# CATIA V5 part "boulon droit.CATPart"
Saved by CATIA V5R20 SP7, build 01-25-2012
Part number: boulon droit
Bounding box of the stored display mesh (mm): x 8.673 to 14.247, y 20.422 to 25.578, z -1.221 to 0.279
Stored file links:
  F:\Travaux\Modélisations\CFAO_2011\CFAO_2011_MMS\CFAO_2011_MMS_DONE\CFAO_2011_MMS_jboiteux\Catia\boulon droit.CATPart
  U:\finthinkmotion\stepper.CATProduct
  F:\Travaux\Modélisations\CFAO_2011\CFAO_2011_MMS\CFAO_2011_MMS_DONE\CFAO_2011_MMS_jboiteux\Catia\bati.CATPart
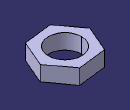
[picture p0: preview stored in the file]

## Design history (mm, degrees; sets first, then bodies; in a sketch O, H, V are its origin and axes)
Parameters
  rayontube = 9 mm {= External.royontubebati}
External parameters (linked from other documents)
  External.royontubebati = 9 mm
Set1
  Plane1: linked copy from another document
  DatumSurface1: linked copy from another document
  Point1: linked copy from another document
Body1 (main body)
  Sketch1 on Plane1, origin (0, 0, -5.7209), H (1, 0, 0), V (0, -1, 0)
    point P1 (11.46, -23)
    point P2 (13.1382, -20.7512)
    point P3 (10.3516, -20.4223)
    point P4 (8.6734, -22.671)
    point P5 (9.7818, -25.2488)
    point P6 (12.5684, -25.5777)
    point P7 (14.2466, -23.329)
    point P8 (11.7449, -20.5868)
    line L1 (13.1382, -20.7512) -> (10.3516, -20.4223)
    line L2 (10.3516, -20.4223) -> (8.6734, -22.671)
    line L3 (8.6734, -22.671) -> (9.7818, -25.2488)
    line L4 (9.7818, -25.2488) -> (12.5684, -25.5777)
    line L5 (12.5684, -25.5777) -> (14.2466, -23.329)
    line L6 (14.2466, -23.329) -> (13.1382, -20.7512)
    construction line L7 (11.46, -23) -> (11.7449, -20.5868)
    construction circle A1 centre (11.46, -23) radius 2.8059
    construction arc A2 centre (12.5684, -25.5777) radius 2.8059 from (9.7818, -25.2488) to (14.2466, -23.329) cw
    construction arc A3 centre (10.3516, -20.4223) radius 2.8059 from (8.6734, -22.671) to (13.1382, -20.7512) ccw
    reference projected point E1 (11.46, -23) from Point1
    circle A4 centre (11.46, -23) radius 1.65
    point P9 (11.46, -23)
    reference projected point E2 (11.46, -23) from Point1
    reference projected point E3 (11.46, -23) from Point1
    distance E3 L2 = 2.43 {= rayontube *0.27}
    radius A4 = 1.65 {= rayontube *11/60}
    coincidence: A1 P2, A1 P3, A1 P4, A1 P5, A1 P6, A1 P7, A2 P1, A3 P1, E1 P1, E2 P9
    midpoint: P8 L1
    parallelism: L1 L4
  Pad1: profile Sketch1, direction (0, 0, 1), up to face of DatumSurface1, opposite side length -6 {= -rayontube *2/3}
